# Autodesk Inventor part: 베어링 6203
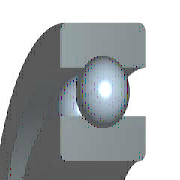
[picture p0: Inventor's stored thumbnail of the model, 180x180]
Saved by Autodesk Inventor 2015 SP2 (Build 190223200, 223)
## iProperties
IsCustomPart: 0
Created: 2009-02
Part Number: 베어링 6203
Material: 강, 연강
Description: 깊은 그루브 볼 베어링
Document SubType Name: Modeling
Standard: KS B 2023
Designer: 한국산업디자인학원 [http://gmhk.co.kr]
Standards Organization: KS
Language: ko-KR
Size Designation: 6203 - 17 x 40 x 12
Categories: <MemberInstance><Categories><Category DisplayName="샤프트 부품" InternalName="7f7aeb1f-a693-4053-b835-cee3144e0d98" Mnemonic="SHFT"><Category DisplayName="베어링" Inter
Density: 1 g/cm^3
Appearance: 크롬 - 광택
Author: pww
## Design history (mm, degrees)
sketch "스케치" dims "d0" = 5.98 (= -0.26 x WD + 0.26 x BD)
  geometry: L1 (3.01, 14.25)-(8.99, 14.25); L2 (6, 14.25)-(6, 11.26); L3 (6, 14.25)-(6, 17.24); L4 (3.778, 12.249)-(0, 12.249); L5 (0, 8.5)-(12, 8.5); L6 (3.778, 16.251)-(0, 16.251); L7 (0, 20)-(12, 20); L8 (12, 8.5)-(12, 12.249); L9 (8.222, 12.249)-(12, 12.249); L10 (8.222, 16.251)-(12, 16.251); L11 (12, 20)-(12, 16.251); L12 (-1.4, 0)-(8.4, 0) reference; L13 (0, -0.3)-(0, 5.3) reference
  constraints: 22 end point, 4 point on line, 2 collinear, 2 perpendicular, 2 symmetric about line, 1 midpoint, 1 parallel, 14 other
  dimensions: "d9" = 17 diameter of L5 L12 (= WD); "d11" = 40 diameter of L7 L12 (= BD); "d12" = 12 distance between parallel lines of L8 L13 (= KB); "d13" = 24.498 diameter of L9 L12 (= 0.326 x BD + 0.674 x WD)
revolve "본체" stored, may be unused: angle "d6" = 90 deg
revolve "볼" stored, may be unused: angle "d7" = 90 deg
pattern_circular "IDS_ARRAYBALL[SIMPL:T]" dims angle "d3" = 360 deg
body "Solid1"
fillet "모깎기1" dims "d1" = 0.6 (= KRS)
other parameters: "WD" = 17 [user parameter; used in 5 equation terms], "BD" = 40 [user parameter; used in 5 equation terms], "KB" = 12 [user parameter; used in 1 equation term], "KRS" = 0.6 [user parameter; used in 1 equation term], "d4" = 0, "d5" = 0, "d8" = 0, "d14" = 0, "d15" = 0, "BBA" = 0 [user parameter], "BC0" = 4750000 [user parameter], "BC" = 9560000 [user parameter], "WR" = 8.5 (= 0.5 x WD) [user parameter]
